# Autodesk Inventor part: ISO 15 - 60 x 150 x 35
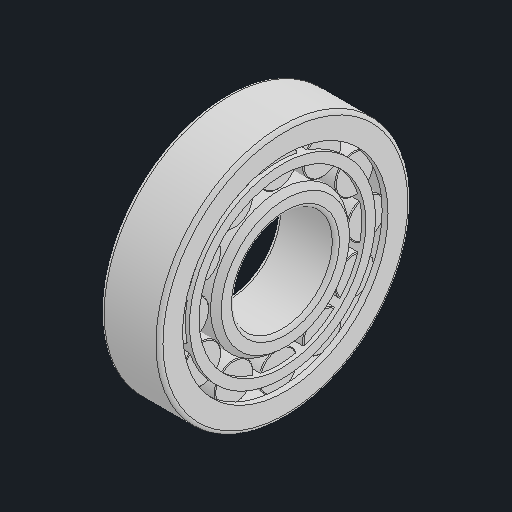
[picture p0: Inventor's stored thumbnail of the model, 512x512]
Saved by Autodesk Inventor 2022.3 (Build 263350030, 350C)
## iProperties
Created: 2020-09
Part Number: ISO 15 - 60 x 150 x 35
Material: Типовые
Document SubType Name: Modeling
Designer: Карташов
Density: 1 g/cm^3
Appearance: По умолчанию
Title: D:\мои документы\Ирина\_WorldSkills\2020_09 ФНЧ\Module A\GIVEN\ISO 15 - 60 x 150 x 35.stp
Author: Дом
Sending System: Autodesk Inventor 2021
Preprocessor: ST-DEVELOPER v18.1
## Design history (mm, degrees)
feature "Твердое тело2"
node "Твердое тело1"
